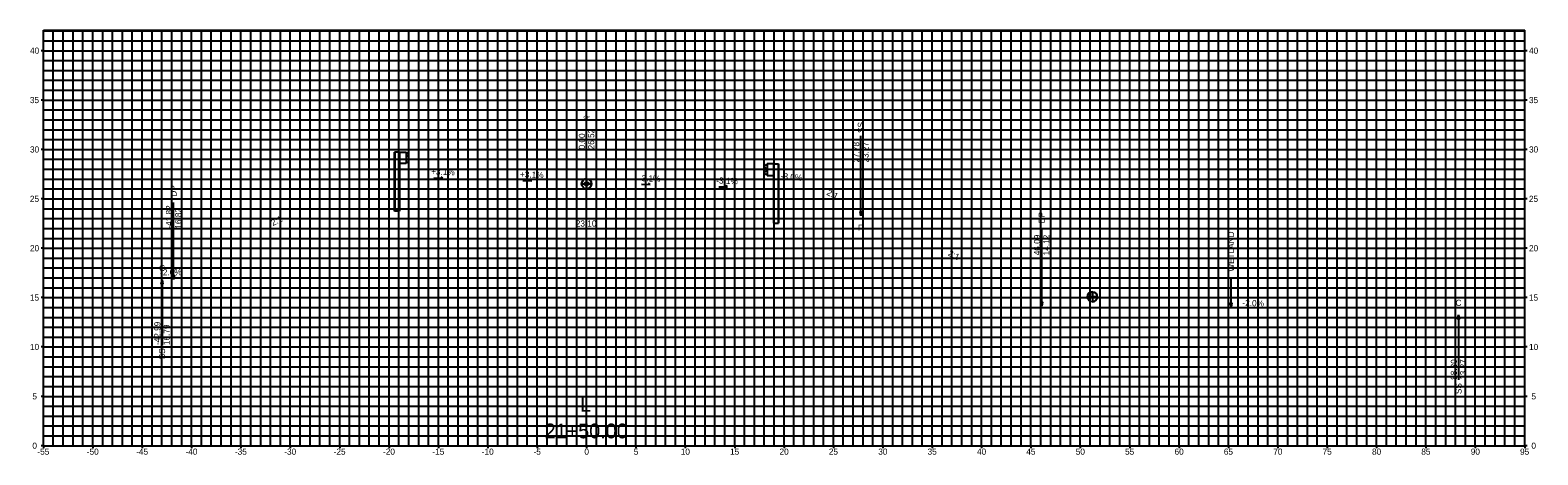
# Model space of a CAD drawing. Extents: x -56 to 96, y -1 to 42.
import ezdxf

# ---------------------------------------------------------------- set-up
doc = ezdxf.new("R2010")
doc.units = 0
for name, color, linetype in [('E_NCDOT_XS_Center_Line_Elevation_Label', 7, 'Continuous'), ('P_NCDOT_XS_Label_Grade_Point', 7, 'Continuous'), ('P_NCDOT_XS_Label_Grading_Side_Slope', 7, 'Continuous'), ('P_NCDOT_XS_Label_Slope_Superelevation', 7, 'Continuous'), ('P_NCDOT_XS_Leader_Line', 7, 'Continuous'), ('P_NCDOT_XS_Sheet_Alignment_Station_Label', 7, 'Continuous'), ('P_NCDOT_XS_Sheet_Annotation_Label', 7, 'Continuous'), ('P_NCDOT_XS_Sheet_Grid_Border', 7, 'Continuous'), ('P_NCDOT_XS_Slope_Label', 7, 'Continuous'), ('P_RDY_DXS_Guardrail_Cell', 7, 'Continuous'), ('P_RDY_XS_EOT_Tick_Mark', 7, 'Continuous'), ('Prop XS Grade Point', 7, 'Continuous'), ('Prop XS Label Slope Superelevation', 7, 'Continuous'), ('Sheet_Grid_Major', 7, 'Continuous'), ('Sheet_Grid_Middle', 7, 'Continuous'), ('Sheet_Grid_Minor', 7, 'Continuous')]:
    doc.layers.add(name, color=color, linetype=linetype)

msp = doc.modelspace()

# ---------------------------------------------------------------- linework, layer by layer
at = {"layer": 'P_NCDOT_XS_Leader_Line'}
for p, q in [((0, 26.52), (0, 32.76)), ((27.78, 23.27), (27.78, 31.37)), ((-41.82, 16.82), (-41.82, 24.62)), ((46.09, 14.12), (46.09, 21.92)), ((65.26, 14.02), (65.26, 17.02)), ((-42.99, 16.79), (-42.99, 10.19)), ((88.3, 13.27), (88.3, 6.67))]:
    msp.add_line(p, q, dxfattribs=at)
for points in [[(0.15, 26.37), (-0.15, 26.37), (-0.15, 26.67), (0.15, 26.67)], [(27.78, 23.27), (27.69, 23.68), (27.87, 23.68)], [(-41.82, 16.82), (-41.9, 17.23), (-41.73, 17.23)], [(-42.99, 16.79), (-42.9, 16.38), (-43.08, 16.38)], [(46.09, 14.12), (46, 14.53), (46.17, 14.53)], [(65.26, 14.02), (65.17, 14.43), (65.35, 14.43)], [(88.3, 13.27), (88.39, 12.86), (88.21, 12.86)]]:
    msp.add_lwpolyline(points, close=True, dxfattribs=at)
at = {"layer": 'P_NCDOT_XS_Sheet_Grid_Border'}
for p, q in [((-55, 42.08), (95, 42.08)), ((-55, 0), (-55, 42.08)), ((95, 0), (95, 42.08)), ((-55, 0), (95, 0))]:
    msp.add_line(p, q, dxfattribs=at)
at = {"layer": 'P_RDY_DXS_Guardrail_Cell'}
for p, q in [((-18.94, 29.74), (-19.44, 29.74)), ((-19.44, 29.74), (-19.42, 29.74)), ((-19.44, 23.74), (-19.44, 29.74)), ((-19.42, 29.74), (-19.42, 23.74)), ((-18.96, 29.74), (-18.94, 29.74)), ((-18.96, 23.74), (-18.96, 29.74)), ((-18.94, 29.74), (-18.27, 29.74)), ((-18.94, 29.74), (-18.94, 23.74)), ((-18.27, 29.74), (-18.27, 28.58)), ((-18.27, 29.66), (-18.18, 29.65)), ((-18.27, 29.21), (-18.27, 29.16)), ((-18.27, 29.16), (-18.27, 29.11)), ((-18.03, 29.42), (-18.24, 29.27)), ((-18.24, 29.05), (-18.03, 28.9)), ((-18.17, 29.64), (-18.03, 29.55)), ((-18.27, 28.58), (-18.94, 28.58)), ((-18.18, 28.67), (-18.27, 28.66)), ((-18.03, 28.77), (-18.17, 28.68)), ((18.17, 28.44), (18.03, 28.34)), ((18.03, 28.21), (18.24, 28.07)), ((18.24, 27.84), (18.03, 27.7)), ((18.03, 27.57), (18.17, 27.47)), ((18.27, 28.46), (18.18, 28.44)), ((18.94, 28.54), (18.28, 28.54)), ((18.28, 28.54), (18.28, 27.37)), ((18.28, 28), (18.28, 27.95)), ((18.28, 27.95), (18.28, 27.91)), ((18.94, 28.54), (19.44, 28.54)), ((18.96, 28.54), (18.94, 28.54)), ((18.94, 28.54), (18.94, 22.54)), ((18.96, 22.54), (18.96, 28.54)), ((19.44, 28.54), (19.43, 28.54)), ((19.43, 28.54), (19.43, 22.54)), ((19.44, 22.54), (19.44, 28.54)), ((18.18, 27.47), (18.27, 27.45)), ((18.28, 27.37), (18.94, 27.37)), ((-18.94, 23.74), (-19.44, 23.74)), ((-19.42, 23.74), (-19.44, 23.74)), ((-18.94, 23.74), (-18.96, 23.74)), ((18.94, 22.54), (19.44, 22.54)), ((18.94, 22.54), (18.96, 22.54)), ((19.43, 22.54), (19.44, 22.54))]:
    msp.add_line(p, q, dxfattribs=at)
for centre, radius, start, end in [((-18.19, 29.21), 0.0787, 124.6522, 179.98), ((-18.19, 29.11), 0.0787, 180.02, 235.3478), ((-18.19, 29.62), 0.0328, 54.7024, 80), ((-18.08, 29.48), 0.0787, 304.6522, 54.7024), ((-18.19, 28.7), 0.0328, 280, 305.2976), ((-18.08, 28.84), 0.0787, 305.2976, 55.3478), ((18.08, 28.27), 0.0787, 125.2976, 235.3478), ((18.08, 27.63), 0.0787, 124.6522, 234.7024), ((18.19, 28.41), 0.0328, 100, 125.2976), ((18.2, 28), 0.0787, 0.02, 55.3478), ((18.2, 27.91), 0.0787, 304.6522, 359.98), ((18.19, 27.5), 0.0328, 234.7024, 260)]:
    msp.add_arc(centre, radius, start, end, dxfattribs=at)
at = {"layer": 'P_RDY_XS_EOT_Tick_Mark'}
for p, q in [((-12, 26.89), (-12, 27.2)), ((12, 26.15), (12, 26.46))]:
    msp.add_line(p, q, dxfattribs=at)
at = {"layer": 'Prop XS Grade Point'}
for p, q in [((-0.5, 26.52), (0.5, 26.52)), ((0, 27.02), (0, 26.02)), ((51.22, 15.58), (51.22, 14.58)), ((50.72, 15.08), (51.72, 15.08))]:
    msp.add_line(p, q, dxfattribs=at)
for points in [[(-0.5, 26.52), (0, 26.52), (0, 27.02)], [(0.5, 26.52), (0, 26.52), (0, 26.02)], [(50.72, 15.08), (51.22, 15.08), (51.22, 15.58)], [(51.72, 15.08), (51.22, 15.08), (51.22, 14.58)]]:
    msp.add_lwpolyline(points, dxfattribs=at)
for centre in [(0, 26.52), (51.22, 15.08)]:
    msp.add_circle(centre, 0.5, dxfattribs=at)
for centre, start, end in [((0, 26.52), 90, 180), ((0, 26.52), 270, 0), ((51.22, 15.08), 90, 180), ((51.22, 15.08), 270, 0)]:
    msp.add_arc(centre, 0.5, start, end, dxfattribs=at)
at = {"layer": 'Prop XS Label Slope Superelevation'}
for p, q in [((-15.45, 27.12), (-14.55, 27.09)), ((-14.55, 27.09), (-14.72, 27.22)), ((-6.45, 26.84), (-5.55, 26.81)), ((-5.55, 26.81), (-5.72, 26.94)), ((5.55, 26.47), (6.45, 26.44)), ((6.45, 26.44), (6.28, 26.57)), ((13.38, 26.23), (14.28, 26.2)), ((14.28, 26.2), (14.11, 26.32))]:
    msp.add_line(p, q, dxfattribs=at)
at = {"layer": 'Sheet_Grid_Major'}
for p, q in [((-50, 0), (-50, 42.08)), ((-40, 0), (-40, 42.08)), ((-30, 0), (-30, 42.08)), ((-20, 0), (-20, 42.08)), ((-10, 0), (-10, 42.08)), ((0, 0), (0, 42.08)), ((10, 0), (10, 42.08)), ((20, 0), (20, 42.08)), ((30, 0), (30, 42.08)), ((40, 0), (40, 42.08)), ((50, 0), (50, 42.08)), ((60, 0), (60, 42.08)), ((70, 0), (70, 42.08)), ((80, 0), (80, 42.08)), ((90, 0), (90, 42.08)), ((-55, 40), (95, 40)), ((-55, 30), (95, 30)), ((-55, 20), (95, 20)), ((-55, 10), (95, 10))]:
    msp.add_line(p, q, dxfattribs=at)
at = {"layer": 'Sheet_Grid_Middle'}
for p, q in [((-50, 0), (-50, 42.08)), ((-45, 0), (-45, 42.08)), ((-40, 0), (-40, 42.08)), ((-35, 0), (-35, 42.08)), ((-30, 0), (-30, 42.08)), ((-25, 0), (-25, 42.08)), ((-20, 0), (-20, 42.08)), ((-15, 0), (-15, 42.08)), ((-10, 0), (-10, 42.08)), ((-5, 0), (-5, 42.08)), ((0, 0), (0, 42.08)), ((5, 0), (5, 42.08)), ((10, 0), (10, 42.08)), ((15, 0), (15, 42.08)), ((20, 0), (20, 42.08)), ((25, 0), (25, 42.08)), ((30, 0), (30, 42.08)), ((35, 0), (35, 42.08)), ((40, 0), (40, 42.08)), ((45, 0), (45, 42.08)), ((50, 0), (50, 42.08)), ((55, 0), (55, 42.08)), ((60, 0), (60, 42.08)), ((65, 0), (65, 42.08)), ((70, 0), (70, 42.08)), ((75, 0), (75, 42.08)), ((80, 0), (80, 42.08)), ((85, 0), (85, 42.08)), ((90, 0), (90, 42.08)), ((-55, 40), (-55.24, 40)), ((-55, 40), (95, 40)), ((95.24, 40), (95, 40)), ((-55, 35), (-55.24, 35)), ((-55, 35), (95, 35)), ((95.24, 35), (95, 35)), ((-55, 30), (-55.24, 30)), ((-55, 30), (95, 30)), ((95.24, 30), (95, 30)), ((-55, 25), (-55.24, 25)), ((-55, 25), (95, 25)), ((95.24, 25), (95, 25)), ((-55, 20), (-55.24, 20)), ((-55, 20), (95, 20)), ((95.24, 20), (95, 20)), ((-55, 15), (-55.24, 15)), ((-55, 15), (95, 15)), ((95.24, 15), (95, 15)), ((-55, 10), (-55.24, 10)), ((-55, 10), (95, 10)), ((95.24, 10), (95, 10)), ((-55, 5), (-55.24, 5)), ((-55, 5), (95, 5)), ((95.24, 5), (95, 5)), ((-55, 0), (-55.24, 0)), ((-55, 0), (-55, -0.24)), ((-50, 0), (-50, -0.24)), ((-45, 0), (-45, -0.24)), ((-40, 0), (-40, -0.24)), ((-35, 0), (-35, -0.24)), ((-30, 0), (-30, -0.24)), ((-25, 0), (-25, -0.24)), ((-20, 0), (-20, -0.24)), ((-15, 0), (-15, -0.24)), ((-10, 0), (-10, -0.24)), ((-5, 0), (-5, -0.24)), ((0, 0), (0, -0.24)), ((5, 0), (5, -0.24)), ((10, 0), (10, -0.24)), ((15, 0), (15, -0.24)), ((20, 0), (20, -0.24)), ((25, 0), (25, -0.24)), ((30, 0), (30, -0.24)), ((35, 0), (35, -0.24)), ((40, 0), (40, -0.24)), ((45, 0), (45, -0.24)), ((50, 0), (50, -0.24)), ((55, 0), (55, -0.24)), ((60, 0), (60, -0.24)), ((65, 0), (65, -0.24)), ((70, 0), (70, -0.24)), ((75, 0), (75, -0.24)), ((80, 0), (80, -0.24)), ((85, 0), (85, -0.24)), ((90, 0), (90, -0.24)), ((95, 0), (95, -0.24)), ((95.24, 0), (95, 0))]:
    msp.add_line(p, q, dxfattribs=at)
at = {"layer": 'Sheet_Grid_Minor'}
for p, q in [((-55, 42), (95, 42)), ((-54, 0), (-54, 42.08)), ((-53, 0), (-53, 42.08)), ((-52, 0), (-52, 42.08)), ((-51, 0), (-51, 42.08)), ((-49, 0), (-49, 42.08)), ((-48, 0), (-48, 42.08)), ((-47, 0), (-47, 42.08)), ((-46, 0), (-46, 42.08)), ((-44, 0), (-44, 42.08)), ((-43, 0), (-43, 42.08)), ((-42, 0), (-42, 42.08)), ((-41, 0), (-41, 42.08)), ((-39, 0), (-39, 42.08)), ((-38, 0), (-38, 42.08)), ((-37, 0), (-37, 42.08)), ((-36, 0), (-36, 42.08)), ((-34, 0), (-34, 42.08)), ((-33, 0), (-33, 42.08)), ((-32, 0), (-32, 42.08)), ((-31, 0), (-31, 42.08)), ((-29, 0), (-29, 42.08)), ((-28, 0), (-28, 42.08)), ((-27, 0), (-27, 42.08)), ((-26, 0), (-26, 42.08)), ((-24, 0), (-24, 42.08)), ((-23, 0), (-23, 42.08)), ((-22, 0), (-22, 42.08)), ((-21, 0), (-21, 42.08)), ((-19, 0), (-19, 42.08)), ((-18, 0), (-18, 42.08)), ((-17, 0), (-17, 42.08)), ((-16, 0), (-16, 42.08)), ((-14, 0), (-14, 42.08)), ((-13, 0), (-13, 42.08)), ((-12, 0), (-12, 42.08)), ((-11, 0), (-11, 42.08)), ((-9, 0), (-9, 42.08)), ((-8, 0), (-8, 42.08)), ((-7, 0), (-7, 42.08)), ((-6, 0), (-6, 42.08)), ((-4, 0), (-4, 42.08)), ((-3, 0), (-3, 42.08)), ((-2, 0), (-2, 42.08)), ((-1, 0), (-1, 42.08)), ((1, 0), (1, 42.08)), ((2, 0), (2, 42.08)), ((3, 0), (3, 42.08)), ((4, 0), (4, 42.08)), ((6, 0), (6, 42.08)), ((7, 0), (7, 42.08)), ((8, 0), (8, 42.08)), ((9, 0), (9, 42.08)), ((11, 0), (11, 42.08)), ((12, 0), (12, 42.08)), ((13, 0), (13, 42.08)), ((14, 0), (14, 42.08)), ((16, 0), (16, 42.08)), ((17, 0), (17, 42.08)), ((18, 0), (18, 42.08)), ((19, 0), (19, 42.08)), ((21, 0), (21, 42.08)), ((22, 0), (22, 42.08)), ((23, 0), (23, 42.08)), ((24, 0), (24, 42.08)), ((26, 0), (26, 42.08)), ((27, 0), (27, 42.08)), ((28, 0), (28, 42.08)), ((29, 0), (29, 42.08)), ((31, 0), (31, 42.08)), ((32, 0), (32, 42.08)), ((33, 0), (33, 42.08)), ((34, 0), (34, 42.08)), ((36, 0), (36, 42.08)), ((37, 0), (37, 42.08)), ((38, 0), (38, 42.08)), ((39, 0), (39, 42.08)), ((41, 0), (41, 42.08)), ((42, 0), (42, 42.08)), ((43, 0), (43, 42.08)), ((44, 0), (44, 42.08)), ((46, 0), (46, 42.08)), ((47, 0), (47, 42.08)), ((48, 0), (48, 42.08)), ((49, 0), (49, 42.08)), ((51, 0), (51, 42.08)), ((52, 0), (52, 42.08)), ((53, 0), (53, 42.08)), ((54, 0), (54, 42.08)), ((56, 0), (56, 42.08)), ((57, 0), (57, 42.08)), ((58, 0), (58, 42.08)), ((59, 0), (59, 42.08)), ((61, 0), (61, 42.08)), ((62, 0), (62, 42.08)), ((63, 0), (63, 42.08)), ((64, 0), (64, 42.08)), ((66, 0), (66, 42.08)), ((67, 0), (67, 42.08)), ((68, 0), (68, 42.08)), ((69, 0), (69, 42.08)), ((71, 0), (71, 42.08)), ((72, 0), (72, 42.08)), ((73, 0), (73, 42.08)), ((74, 0), (74, 42.08)), ((76, 0), (76, 42.08)), ((77, 0), (77, 42.08)), ((78, 0), (78, 42.08)), ((79, 0), (79, 42.08)), ((81, 0), (81, 42.08)), ((82, 0), (82, 42.08)), ((83, 0), (83, 42.08)), ((84, 0), (84, 42.08)), ((86, 0), (86, 42.08)), ((87, 0), (87, 42.08)), ((88, 0), (88, 42.08)), ((89, 0), (89, 42.08)), ((91, 0), (91, 42.08)), ((92, 0), (92, 42.08)), ((93, 0), (93, 42.08)), ((94, 0), (94, 42.08)), ((-55, 41), (95, 41)), ((-55, 39), (95, 39)), ((-55, 38), (95, 38)), ((-55, 37), (95, 37)), ((-55, 36), (95, 36)), ((-55, 34), (95, 34)), ((-55, 33), (95, 33)), ((-55, 32), (95, 32)), ((-55, 31), (95, 31)), ((-55, 29), (95, 29)), ((-55, 28), (95, 28)), ((-55, 27), (95, 27)), ((-55, 26), (95, 26)), ((-55, 24), (95, 24)), ((-55, 23), (95, 23)), ((-55, 22), (95, 22)), ((-55, 21), (95, 21)), ((-55, 19), (95, 19)), ((-55, 18), (95, 18)), ((-55, 17), (95, 17)), ((-55, 16), (95, 16)), ((-55, 14), (95, 14)), ((-55, 13), (95, 13)), ((-55, 12), (95, 12)), ((-55, 11), (95, 11)), ((-55, 9), (95, 9)), ((-55, 8), (95, 8)), ((-55, 7), (95, 7)), ((-55, 6), (95, 6)), ((-55, 4), (95, 4)), ((-55, 3), (95, 3)), ((-55, 2), (95, 2)), ((-55, 1), (95, 1))]:
    msp.add_line(p, q, dxfattribs=at)

# ---------------------------------------------------------------- texts
at = {"layer": 'E_NCDOT_XS_Center_Line_Elevation_Label'}
msp.add_text('23.10', height=0.624, dxfattribs=at).set_placement((-1.09, 22.19))
at = {"layer": 'P_NCDOT_XS_Label_Grade_Point'}
msp.add_text('GP', height=0.312, dxfattribs=at).set_placement((-0.31, 33.09))
for s, p in [('0.00', (-0.16, 30)), ('26.52', (0.78, 30))]:
    msp.add_text(s, height=0.624, rotation=90, dxfattribs=at).set_placement(p)
at = {"layer": 'P_NCDOT_XS_Label_Grading_Side_Slope'}
for s, p in [('SS', (28.09, 31.67)), ('27.78', (27.62, 28.67)), ('23.27', (28.56, 28.67)), ('DP', (-41.5, 25.22)), ('-41.82', (-41.97, 21.98)), ('16.82', (-41.04, 21.98)), ('DP', (46.4, 22.52)), ('WETLAND', (65.57, 17.62)), ('46.09', (45.93, 19.28)), ('14.12', (46.87, 19.28)), ('-42.99', (-43.15, 10.19)), ('16.79', (-42.21, 10.19)), ('SS', (-42.68, 8.75)), ('88.30', (88.14, 6.67)), ('13.27', (89.08, 6.67)), ('SS', (88.61, 5.23))]:
    msp.add_text(s, height=0.624, rotation=90, dxfattribs=at).set_placement(p)
for s, p in [('F', (27.48, 21.76)), ('C', (-43.29, 17.68)), ('C', (88, 14.16))]:
    msp.add_text(s, height=0.624, dxfattribs=at).set_placement(p)
at = {"layer": 'P_NCDOT_XS_Label_Slope_Superelevation'}
for s, p in [('+3.1%', (-6.75, 27.17)), ('-3.1%', (5.29, 26.79))]:
    msp.add_text(s, height=0.624, rotation=358.2275, dxfattribs=at).set_placement(p)
at = {"layer": 'P_NCDOT_XS_Sheet_Alignment_Station_Label'}
for s, p in [('L', (-0.66, 3.45)), ('21+50.00', (-4.25, 0.75))]:
    msp.add_text(s, height=1.5, dxfattribs=at).set_placement(p)
at = {"layer": 'P_NCDOT_XS_Sheet_Annotation_Label'}
for s, p in [('40', (-56.36, 39.69)), ('40', (95.44, 39.69)), ('35', (-56.37, 34.69)), ('35', (95.43, 34.69)), ('30', (-56.36, 29.69)), ('30', (95.44, 29.69)), ('25', (-56.37, 24.69)), ('25', (95.43, 24.69)), ('20', (-56.36, 19.69)), ('20', (95.44, 19.69)), ('15', (-56.37, 14.69)), ('15', (95.43, 14.69)), ('10', (-56.36, 9.69)), ('10', (95.44, 9.69)), ('5', (-56.12, 4.69)), ('5', (95.68, 4.69)), ('0', (-56.12, -0.31)), ('0', (95.68, -0.31)), ('-55', (-55.61, -0.91)), ('-50', (-50.61, -0.91)), ('-45', (-45.61, -0.91)), ('-40', (-40.61, -0.91)), ('-35', (-35.61, -0.91)), ('-30', (-30.61, -0.91)), ('-25', (-25.61, -0.91)), ('-20', (-20.61, -0.91)), ('-15', (-15.61, -0.91)), ('-10', (-10.61, -0.91)), ('-5', (-5.37, -0.91)), ('0', (-0.22, -0.91)), ('5', (4.78, -0.91)), ('10', (9.54, -0.91)), ('15', (14.53, -0.91)), ('20', (19.54, -0.91)), ('25', (24.53, -0.91)), ('30', (29.54, -0.91)), ('35', (34.53, -0.91)), ('40', (39.54, -0.91)), ('45', (44.53, -0.91)), ('50', (49.54, -0.91)), ('55', (54.53, -0.91)), ('60', (59.54, -0.91)), ('65', (64.53, -0.91)), ('70', (69.54, -0.91)), ('75', (74.53, -0.91)), ('80', (79.54, -0.91)), ('85', (84.53, -0.91)), ('90', (89.54, -0.91)), ('95', (94.53, -0.91))]:
    msp.add_text(s, height=0.624, dxfattribs=at).set_placement(p)
at = {"layer": 'P_NCDOT_XS_Slope_Label'}
for s, rotation, p in [('+3.1%', 358.2275, (-15.75, 27.45)), ('-8.0%', 355.4261, (19.64, 27)), ('-3.1%', 358.2275, (13.13, 26.55)), ('2:1', 333.4349, (24.25, 25.44)), ('2:1', 26.5651, (-31.77, 22.24)), ('2:1', 333.4349, (36.54, 19.29)), ('2:1', 333.4349, (36.54, 19.29)), ('-2.0%', 1.1458, (-43.18, 17.23)), ('-2.0%', 358.8542, (66.41, 14.15))]:
    msp.add_text(s, height=0.624, rotation=rotation, dxfattribs=at).set_placement(p)

doc.saveas('drawing.dxf')
